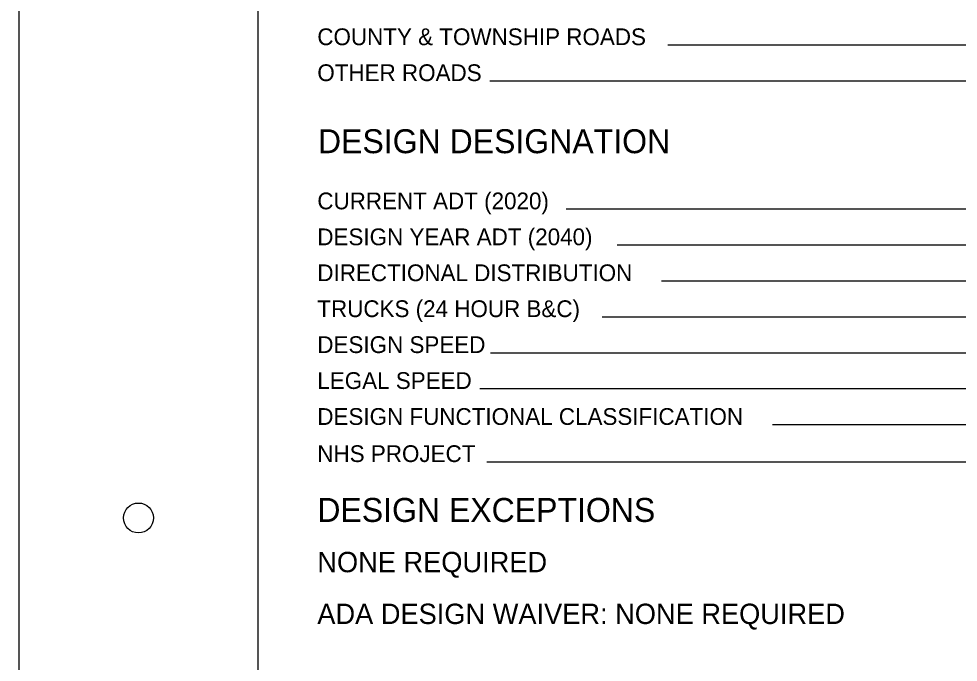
# Model space of a CAD drawing. Extents: x -9.1 to 34, y -3.1 to 22.
# Drawn here: x 0 to 7.85, y 5.55 to 10.92 of the extents above; entities that cross this region are included whole.
import ezdxf

# ---------------------------------------------------------------- set-up
doc = ezdxf.new("R2010")
doc.units = 0
for name, color, linetype in [('SH_Border', 7, 'Continuous'), ('SH_Cut_Line', 7, 'Continuous'), ('SH_Data', 7, 'Continuous')]:
    doc.layers.add(name, color=color, linetype=linetype)

msp = doc.modelspace()

# ---------------------------------------------------------------- linework, layer by layer
at = {"layer": 'SH_Border'}
msp.add_lwpolyline([(2, 21.5), (33.5, 21.5), (33.5, 0.5), (2, 0.5)], close=True, dxfattribs=at)
msp.add_circle((1, 6.75), 0.125, dxfattribs=at)
at = {"layer": 'SH_Cut_Line'}
msp.add_lwpolyline([(0, 0), (34, 0), (34, 22), (0, 22)], close=True, dxfattribs=at)
at = {"layer": 'SH_Data'}
for p, q in [((8.2, 10.6975), (5.424, 10.6975)), ((8.2, 10.3975), (3.9348, 10.3975)), ((8.9626, 9.3271), (4.5737, 9.3271)), ((8.9626, 9.0271), (4.9987, 9.0271)), ((8.9626, 8.7271), (5.3711, 8.7271)), ((8.9626, 8.4271), (4.8746, 8.4271)), ((8.9626, 8.1271), (3.9417, 8.1271)), ((8.9626, 7.8271), (3.8514, 7.8271)), ((8.9626, 7.5271), (6.2963, 7.5271)), ((8.9626, 7.217), (3.9116, 7.217))]:
    msp.add_line(p, q, dxfattribs=at)

# ---------------------------------------------------------------- texts
for s, height, p in [('COUNTY & TOWNSHIP ROADS', 0.14, (2.4944, 10.6975)), ('OTHER ROADS', 0.14, (2.4944, 10.3975)), ('DESIGN DESIGNATION', 0.2, (2.5, 9.7955)), ('CURRENT ADT (2020)', 0.14, (2.4944, 9.3271)), ('DESIGN YEAR ADT (2040)', 0.14, (2.4944, 9.0271)), ('DIRECTIONAL DISTRIBUTION', 0.14, (2.4944, 8.7271)), ('TRUCKS (24 HOUR B&C)', 0.14, (2.4944, 8.4271)), ('DESIGN SPEED', 0.14, (2.4944, 8.1271)), ('LEGAL SPEED', 0.14, (2.4944, 7.8271)), ('DESIGN FUNCTIONAL CLASSIFICATION', 0.14, (2.4944, 7.5271)), ('NHS PROJECT', 0.14, (2.4944, 7.217)), ('DESIGN EXCEPTIONS', 0.2, (2.4944, 6.717)), ('NONE REQUIRED', 0.17, (2.4944, 6.297)), ('ADA DESIGN WAIVER: NONE REQUIRED', 0.17, (2.4944, 5.8646))]:
    msp.add_text(s, height=height, dxfattribs=at).set_placement(p)

doc.saveas('drawing.dxf')
